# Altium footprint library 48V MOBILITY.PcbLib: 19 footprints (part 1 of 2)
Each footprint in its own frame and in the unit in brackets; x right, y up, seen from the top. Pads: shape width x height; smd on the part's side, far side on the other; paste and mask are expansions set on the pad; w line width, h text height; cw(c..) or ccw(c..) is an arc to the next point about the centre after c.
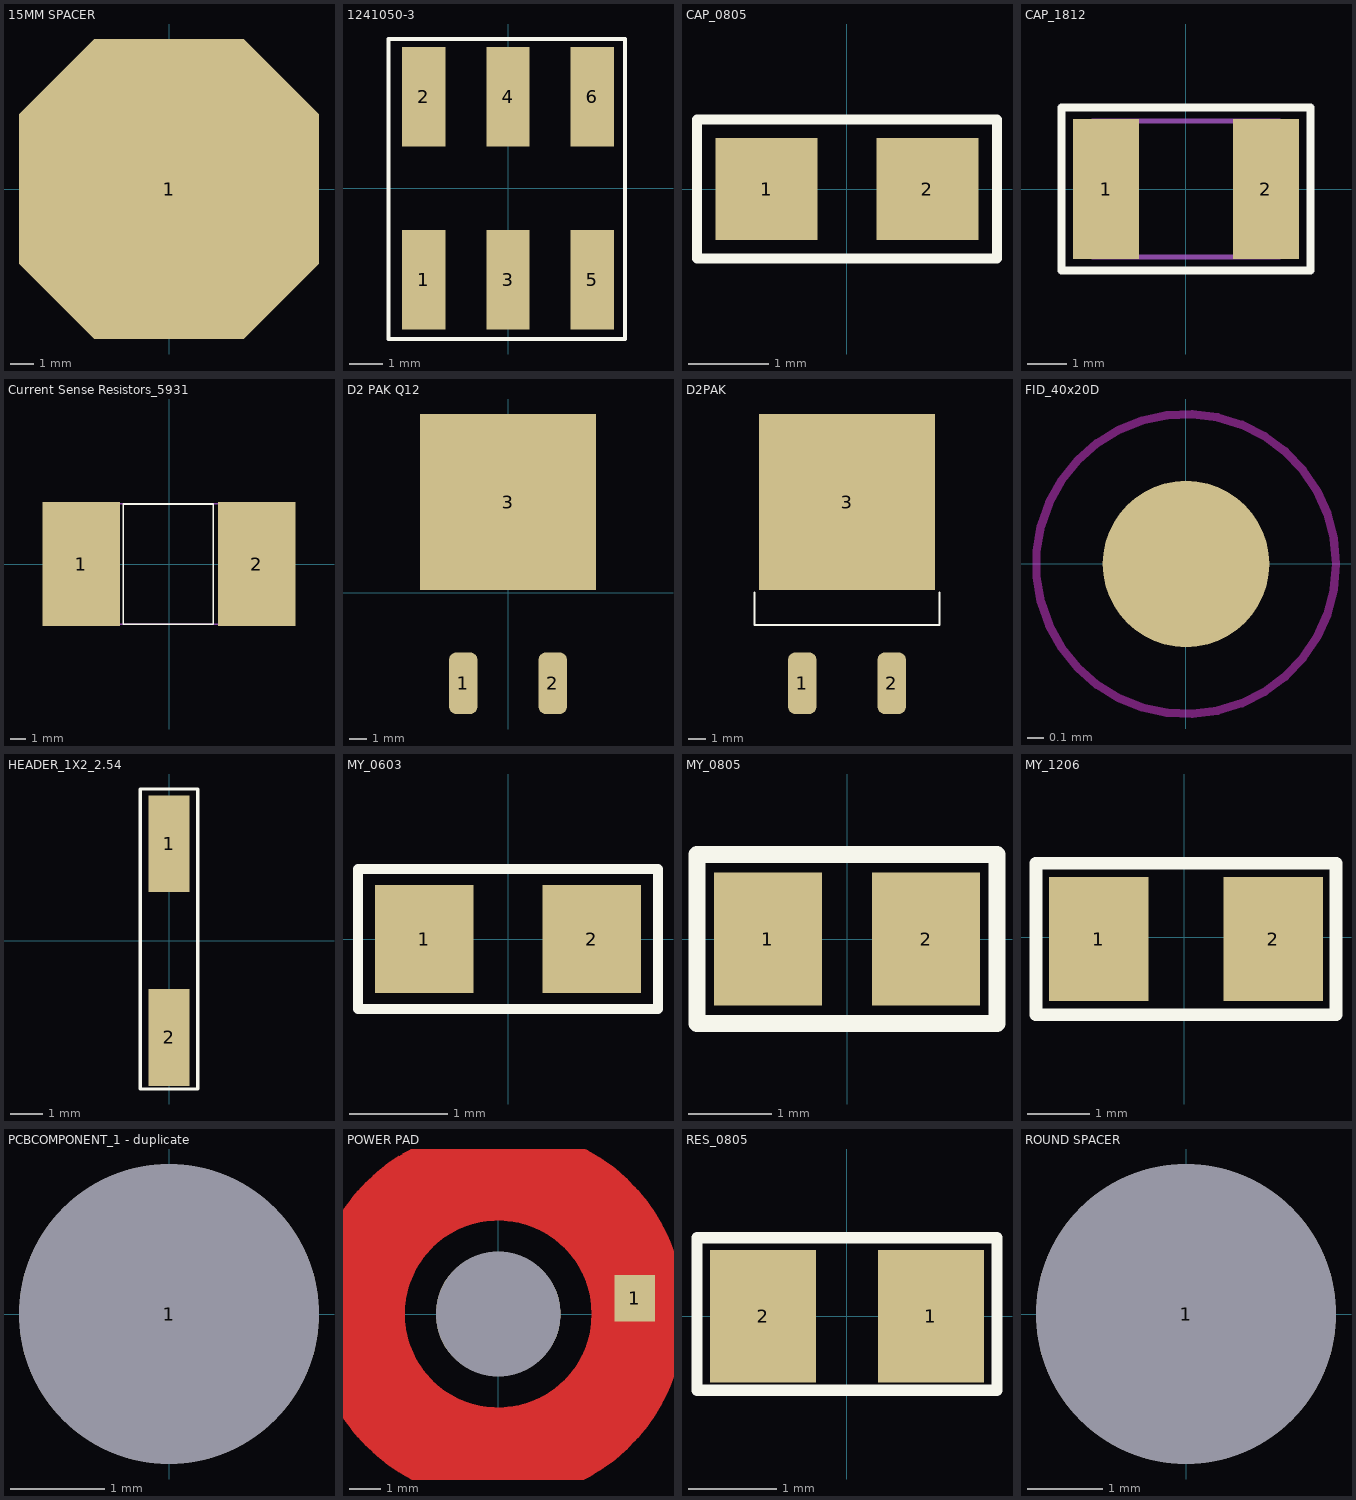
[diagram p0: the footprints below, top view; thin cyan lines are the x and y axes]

## 15MM SPACER [mm]
pads (1):
  oct 13x13 smd: 1(0,0)

## 1241050-3 [mm] "1241050-3"
pads (6):
  rect 1.3x3 smd: 1(-2.54,-2.754) 2(-2.54,2.754) 3(0,-2.754) 4(0,2.754) 5(2.54,-2.754) 6(2.54,2.754)
Top Overlay:
  pour cut-out: -3.81,4.318
  lines w0.125: -3.607,-4.547 3.531,-4.547 3.531,4.496 -3.607,4.496 -3.607,-4.547
3D body "61030621121 (rev1).stp": height 9.57, standoff -0.03, extent -3.81,-3.75 3.81,3.75

## CAP_0805 [mm] "Ceramic Capacitor"
height 0.7
pads (2):
  rect 1.27x1.27 smd mask+0.076: 1(-1,0) 2(1,0)
Top Overlay:
  lines w0.127: 1.845,-0.864 -0.289,-0.864 -1.864,-0.864 -1.864,0.864 0.27,0.864 1.845,0.864 ; 1.864,-0.864 1.864,0.864
3D body "0805 SMD Capacitor.STEP": height 0.78, standoff 0, extent -1,-0.625 1,0.625

## CAP_1812 [mm] "CAP_1812"
pads (2):
  rect 1.7x3.6 smd: 1(-2.057,0) 2(2.057,0)
Top Overlay:
  lines w0.203: -3.2,-2.1 3.2,-2.1 3.2,2.1 -3.2,2.1 -3.2,-2.1
Mechanical 13:
  lines w0.127: -2.4,-1.75 -2.4,1.75 2.4,1.75 2.4,-1.75 -2.4,-1.75
3D body "step_temp.STEP": height 1.1, standoff 0, extent -2.25,-1.6 2.25,1.6

## Current Sense Resistors_5931 [mm]
pads (2):
  rect 5x8 smd: 1(-5.65,0) 2(5.65,0)
Top Overlay:
  lines w0.1: -2.946,-3.886 -2.946,3.861 2.845,3.861 2.845,-3.886 -2.946,-3.886
Mechanical 13:
  lines w0.1: -7.5,-3.875 -7.5,3.875 7.5,3.875 7.5,-3.875 -7.5,-3.875
3D body "PU5931FKNT50U5L.stp": height 1.13, standoff 0, extent -7.5,-3.875 7.5,3.875

## D2 PAK Q12 [mm]
pads (3):
  rrect50% 1.6x3.5 smd: 1(-2.54,-5.137) 2(2.54,-5.137)
  rect 10x10 smd paste-7: 3(0,5.138)
Top Paste:
  region: -2.362,2.873 -2.362,1.492 -3.83,1.492 -3.83,2.873
  region: -2.362,4.843 -2.362,3.464 -3.83,3.464 -3.83,4.843
  region: 3.834,2.873 3.834,1.492 2.36,1.492 2.36,2.873
  region: 3.835,4.843 3.835,3.465 2.36,3.465 2.36,4.843
  region: 1.766,4.843 1.766,3.464 0.295,3.464 0.295,4.843
  region: -0.295,4.843 -0.295,3.465 -1.765,3.465 -1.765,4.843
  region: -0.296,2.873 -0.296,1.492 -1.765,1.492 -1.765,2.873
  region: 1.767,2.873 1.767,1.492 0.295,1.492 0.295,2.873
  region: 3.837,8.783 3.837,7.413 2.36,7.413 2.36,8.783
  region: 3.836,6.813 3.836,5.439 2.36,5.439 2.36,6.813
  region: -2.362,8.783 -2.362,7.407 -3.83,7.407 -3.83,8.783
  region: -2.362,6.813 -2.362,5.437 -3.83,5.437 -3.83,6.813
  region: -0.295,6.813 -0.295,5.439 -1.765,5.439 -1.765,6.813
  region: 1.767,6.813 1.767,5.437 0.295,5.437 0.295,6.813
  region: 1.766,8.783 1.766,7.406 0.295,7.406 0.295,8.783
  region: -0.295,8.783 -0.295,7.412 -1.765,7.412 -1.765,8.783
3D body "Infineon-STP_PG-TO263-3-2-P-v01_00-EN.stp": height 4.51, standoff 0, extent -5,-4.953 5,9.997

## D2PAK [mm]
pads (3):
  rrect50% 1.6x3.5 smd: 1(30.861,-125.152) 2(35.941,-125.152)
  rect 10x10 smd paste-7: 3(33.401,-114.877)
Top Overlay:
  lines w0.127: 28.151,-120.002 28.151,-121.852 38.651,-121.852 38.651,-120.002
Top Paste:
  region: 33.106,-111.232 33.106,-112.603 31.636,-112.603 31.636,-111.232
  region: 35.167,-111.232 35.167,-112.609 33.696,-112.609 33.696,-111.232
  region: 35.168,-113.202 35.168,-114.578 33.696,-114.578 33.696,-113.202
  region: 33.106,-113.202 33.106,-114.576 31.636,-114.576 31.636,-113.202
  region: 31.039,-113.202 31.039,-114.578 29.571,-114.578 29.571,-113.202
  region: 31.039,-111.232 31.039,-112.608 29.571,-112.608 29.571,-111.232
  region: 37.237,-113.202 37.237,-114.576 35.761,-114.576 35.761,-113.202
  region: 37.238,-111.232 37.238,-112.602 35.761,-112.602 35.761,-111.232
  region: 35.168,-117.142 35.168,-118.523 33.696,-118.523 33.696,-117.142
  region: 33.105,-117.142 33.105,-118.523 31.636,-118.523 31.636,-117.142
  region: 33.106,-115.172 33.106,-116.55 31.636,-116.55 31.636,-115.172
  region: 35.167,-115.172 35.167,-116.551 33.696,-116.551 33.696,-115.172
  region: 37.236,-115.172 37.236,-116.55 35.761,-116.55 35.761,-115.172
  region: 37.235,-117.142 37.235,-118.523 35.761,-118.523 35.761,-117.142
  region: 31.039,-115.172 31.039,-116.551 29.571,-116.551 29.571,-115.172
  region: 31.039,-117.142 31.039,-118.523 29.571,-118.523 29.571,-117.142
Mechanical 13:
  lines w0.127: 28.401,-121.852 38.401,-121.852
3D body "Infineon-STP_PG-TO263-3-2-P-v01_00-EN.stp": height 4.51, standoff 0, extent 28.401,-124.968 38.401,-110.018

## FID_40x20D [mm]
pads (1):
  round 1 smd mask+0: ""(0,0)
Top Solder:
  circle w0.9: c0,0 r0.45
Keep-Out Layer:
  circle w0.05: c0,0 r0.9

## HEADER_1X2_2.54 [mm] "HEADER_2X2_2.54"
pads (2):
  rect 1.27x3 smd: 1(0,3) 2(0,-3)
Top Overlay:
  lines w0.1: -0.889,-4.6 0.889,-4.6 0.889,4.7 -0.889,4.7 -0.889,-4.6

## MY_0603 [mm]
pads (2):
  rect 1x1.1 smd: 1(-0.85,0) 2(0.85,0)
Top Overlay:
  lines w0.102: -1.524,-0.711 1.524,-0.711 1.524,0.711 -1.524,0.711 -1.524,-0.711
3D body "User Library-SMD RESISTOR-1.STEP": height 0.44, standoff -0.01, extent -0.8,-0.4 0.8,0.4

## MY_0805 [mm]
height 0.038
pads (2):
  rect 1.3x1.6 smd: 1(-0.95,0) 2(0.95,0)
Top Overlay:
  lines w0.203: -1.803,-1.016 -1.803,1.016 1.803,1.016 1.803,-1.016 -1.803,-1.016
3D body "User Library-SMD RESISTOR-1.STEP": height 0.59, standoff -0.01, extent -1,-0.625 1,0.625

## MY_1206 [mm]
height 0.051
pads (2):
  rect 1.6x2 smd: 1(-1.375,-0.025) 2(1.425,-0.025)
Top Overlay:
  lines w0.203: -2.388,-1.245 2.438,-1.245 2.438,1.194 -2.388,1.194 -2.388,-1.245
3D body "User Library-SMD RESISTOR-1.STEP": height 0.59, standoff -0.01, extent -1.575,-0.825 1.625,0.775

## PCBCOMPONENT_1 - duplicate [mm]
pads (1):
  round 3.2 hole 3.2: 1(0,0)

## POWER PAD [mm]
pads (2):
  rect 1.3x1.5 smd mask+0.076: 1(4.379,0.508)
  round 4 hole 4 unplated: ""(0,0)
Top Layer:
  circle w3: c0,0 r4.5

## RES_0805 [mm] "Resister"
height 0.65
pads (2):
  rect 1.2x1.5 smd mask+0.076: 1(0.95,0) 2(-0.95,0)
Top Overlay:
  lines w0.127: -1.7,-0.838 -1.7,0.889 1.7,0.889 1.7,-0.838 -1.7,-0.838
3D body "RES0805.stp": height 0.5, standoff 0, extent -1,-0.63 1,0.62

## ROUND SPACER [mm]
pads (1):
  round 4 hole 4: 1(0,0)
